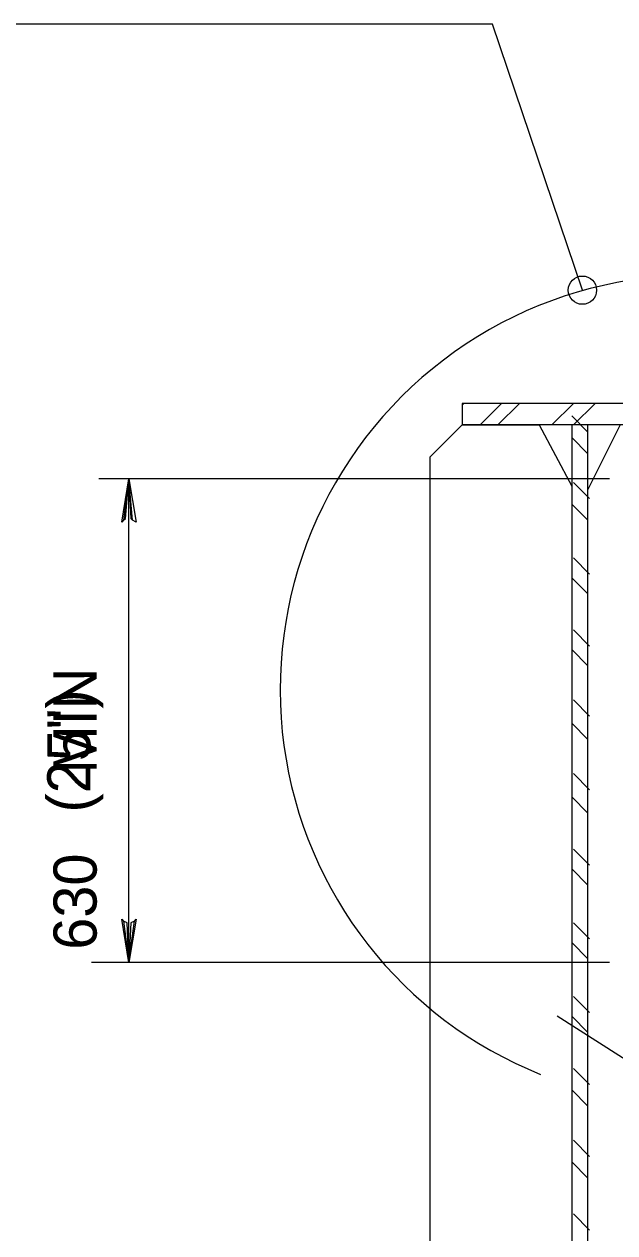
# Model space of a CAD drawing. Extents: x 634656 to 641360, y 298715 to 301183.
# Drawn here: x 640253.8 to 640294.9, y 299751.6 to 299835.7 of the extents above; entities that cross this region are included whole.
import ezdxf

# ---------------------------------------------------------------- set-up
doc = ezdxf.new("R2010")
doc.units = 0
for name, color, linetype in [('1', 7, 'Continuous'), ('2', 7, 'Continuous'), ('40', 7, 'Continuous')]:
    doc.layers.add(name, color=color, linetype=linetype)

msp = doc.modelspace()

# ---------------------------------------------------------------- linework, layer by layer
at = {"layer": '1'}
msp.add_circle((640292.613, 299817.201), 0.984, dxfattribs=at)
at = {"layer": '2'}
for p, q in [((640286.363, 299835.701), (640247.488, 299835.701)), ((640292.613, 299817.201), (640286.363, 299835.701)), ((640300.738, 299809.326), (640284.238, 299809.326)), ((640284.238, 299809.326), (640284.238, 299807.826)), ((640284.238, 299807.826), (640281.988, 299805.576)), ((640284.238, 299807.826), (640289.613, 299807.826)), ((640300.738, 299807.826), (640284.238, 299807.826)), ((640289.613, 299807.826), (640291.863, 299803.576)), ((640291.863, 299807.826), (640291.863, 299713.576)), ((640295.238, 299807.826), (640292.988, 299803.326)), ((640292.988, 299713.576), (640292.988, 299807.826)), ((640281.988, 299805.576), (640281.988, 299713.576)), ((640294.488, 299804.076), (640258.976, 299804.076)), ((640261.076, 299770.451), (640261.076, 299804.076)), ((640294.488, 299770.451), (640258.478, 299770.451)), ((640298.113, 299762.076), (640290.863, 299766.701))]:
    msp.add_line(p, q, dxfattribs=at)
for points in [[(640284.238, 299809.201), (640284.363, 299809.326)], [(640285.488, 299807.826), (640286.988, 299809.326)], [(640286.738, 299807.826), (640288.238, 299809.326)], [(640290.488, 299807.826), (640291.988, 299809.326)], [(640291.988, 299807.826), (640293.488, 299809.326)], [(640292.988, 299807.326), (640291.863, 299808.451)], [(640292.988, 299805.826), (640291.863, 299806.951)], [(640260.701, 299801.201), (640260.826, 299801.326), (640261.076, 299804.076), (640260.701, 299801.201), (640260.576, 299801.076), (640261.076, 299804.076), (640261.201, 299801.326), (640261.326, 299801.201), (640261.076, 299804.076), (640261.576, 299801.076), (640261.326, 299801.201)], [(640293.113, 299802.701), (640291.988, 299803.826)], [(640292.988, 299801.201), (640291.863, 299802.326)], [(640293.113, 299797.451), (640291.988, 299798.576)], [(640292.988, 299796.076), (640291.863, 299797.201)], [(640293.113, 299792.451), (640291.988, 299793.576)], [(640292.988, 299791.076), (640291.863, 299792.201)], [(640293.113, 299787.576), (640291.988, 299788.701)], [(640292.988, 299785.951), (640291.863, 299787.076)], [(640293.113, 299782.451), (640291.988, 299783.576)], [(640292.988, 299780.826), (640291.863, 299781.951)], [(640293.113, 299777.201), (640291.988, 299778.326)], [(640292.988, 299775.826), (640291.863, 299776.951)], [(640261.451, 299773.326), (640261.201, 299773.201), (640261.076, 299770.451), (640261.451, 299773.326), (640261.576, 299773.451), (640261.076, 299770.451), (640260.951, 299773.201), (640260.701, 299773.326), (640261.076, 299770.451), (640260.576, 299773.451), (640260.701, 299773.326)], [(640293.113, 299772.076), (640291.988, 299773.201)], [(640292.988, 299770.701), (640291.863, 299771.826)], [(640293.113, 299766.951), (640291.988, 299768.076)], [(640292.988, 299765.576), (640291.863, 299766.701)], [(640293.113, 299761.951), (640291.988, 299763.076)], [(640292.988, 299760.451), (640291.863, 299761.576)], [(640293.113, 299756.951), (640291.988, 299758.076)], [(640292.988, 299755.451), (640291.863, 299756.576)], [(640293.113, 299751.826), (640291.988, 299752.951)]]:
    msp.add_lwpolyline(points, dxfattribs=at)
msp.add_arc((640300.409, 299789.419), 28.82, 66.87353, 248.19637, dxfattribs=at)

# ---------------------------------------------------------------- texts
msp.add_text('630     MIN', height=3, rotation=90, dxfattribs=at).set_placement((640258.826, 299771.326))
at = {"layer": '40'}
msp.add_text('(25")', height=3, rotation=90, dxfattribs=at).set_placement((640258.391, 299780.871))

doc.saveas('drawing.dxf')
